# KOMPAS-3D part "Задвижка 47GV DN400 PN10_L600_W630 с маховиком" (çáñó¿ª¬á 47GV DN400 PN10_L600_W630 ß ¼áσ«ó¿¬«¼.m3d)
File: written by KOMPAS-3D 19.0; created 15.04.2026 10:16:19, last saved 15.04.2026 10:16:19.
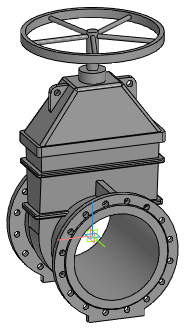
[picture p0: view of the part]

Document properties: Автор: Евгений; Полное имя файла: Z:\3.Личные\kachalov\3d для проектировщиков\2.1 Тип 47GV, 47GV.Z\Задвижка 47GV_DN40-DN600\stp_Задвижка 47GV\Задвижка 47GV DN400 PN10_L600_W630 с маховиком.m3d

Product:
- Part/product: Задвижка 47GV DN400 PN10_L600_W630 с маховиком

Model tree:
1. Операция без истории:1  (labels: Задвижка 47GV DN400 PN10_L600_W630 с маховиком)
